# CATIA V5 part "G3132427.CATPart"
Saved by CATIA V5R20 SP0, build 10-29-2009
Part number: G3132427
Revision: 3
Definition: design
Nomenclature: G3132427
Source: made
Description: NOT SPECIFIED
Bounding box of the stored display mesh (mm): x -22 to 27, y -17.322 to 17.322, z -17.5 to 17.5
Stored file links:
  C:\Users\Raffaele\Desktop\3D X SITO CF\BOLEX\24-BUSH REF 313\G3132427.CATPart
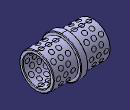
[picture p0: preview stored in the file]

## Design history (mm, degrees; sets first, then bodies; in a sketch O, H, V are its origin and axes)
Body1 "MANIFOLD_SOLID_BREP #11589" (main body)
  Solid1: solid without history
Body2 "MANIFOLD_SOLID_BREP #11740"
  Solid2: solid without history
Body3 "MANIFOLD_SOLID_BREP #11891"
  Solid3: solid without history
Body4 "MANIFOLD_SOLID_BREP #12042"
  Solid4: solid without history
Body5 "MANIFOLD_SOLID_BREP #12193"
  Solid5: solid without history
Body6 "MANIFOLD_SOLID_BREP #12342"
  Solid6: solid without history
Body7 "MANIFOLD_SOLID_BREP #12491"
  Solid7: solid without history
Body8 "MANIFOLD_SOLID_BREP #12640"
  Solid8: solid without history
Body9 "MANIFOLD_SOLID_BREP #12789"
  Solid9: solid without history
Body10 "MANIFOLD_SOLID_BREP #12938"
  Solid10: solid without history
Body11 "MANIFOLD_SOLID_BREP #13087"
  Solid11: solid without history
Body12 "MANIFOLD_SOLID_BREP #13236"
  Solid12: solid without history
Body13 "MANIFOLD_SOLID_BREP #13385"
  Solid13: solid without history
Body14 "MANIFOLD_SOLID_BREP #13534"
  Solid14: solid without history
Body15 "MANIFOLD_SOLID_BREP #13683"
  Solid15: solid without history
Body16 "MANIFOLD_SOLID_BREP #13832"
  Solid16: solid without history
Body17 "MANIFOLD_SOLID_BREP #13981"
  Solid17: solid without history
Body18 "MANIFOLD_SOLID_BREP #14130"
  Solid18: solid without history
Body19 "MANIFOLD_SOLID_BREP #14279"
  Solid19: solid without history
Body20 "MANIFOLD_SOLID_BREP #14428"
  Solid20: solid without history
Body21 "MANIFOLD_SOLID_BREP #14577"
  Solid21: solid without history
Body22 "MANIFOLD_SOLID_BREP #14726"
  Solid22: solid without history
Body23 "MANIFOLD_SOLID_BREP #14875"
  Solid23: solid without history
Body24 "MANIFOLD_SOLID_BREP #15024"
  Solid24: solid without history
Body25 "MANIFOLD_SOLID_BREP #15173"
  Solid25: solid without history
Body26 "MANIFOLD_SOLID_BREP #15322"
  Solid26: solid without history
Body27 "MANIFOLD_SOLID_BREP #15471"
  Solid27: solid without history
Body28 "MANIFOLD_SOLID_BREP #15620"
  Solid28: solid without history
Body29 "MANIFOLD_SOLID_BREP #15769"
  Solid29: solid without history
Body30 "MANIFOLD_SOLID_BREP #15918"
  Solid30: solid without history
Body31 "MANIFOLD_SOLID_BREP #16067"
  Solid31: solid without history
Body32 "MANIFOLD_SOLID_BREP #16218"
  Solid32: solid without history
Body33 "MANIFOLD_SOLID_BREP #16369"
  Solid33: solid without history
Body34 "MANIFOLD_SOLID_BREP #16518"
  Solid34: solid without history
Body35 "MANIFOLD_SOLID_BREP #16667"
  Solid35: solid without history
Body36 "MANIFOLD_SOLID_BREP #16816"
  Solid36: solid without history
Body37 "MANIFOLD_SOLID_BREP #16965"
  Solid37: solid without history
Body38 "MANIFOLD_SOLID_BREP #17114"
  Solid38: solid without history
Body39 "MANIFOLD_SOLID_BREP #17263"
  Solid39: solid without history
Body40 "MANIFOLD_SOLID_BREP #17412"
  Solid40: solid without history
Body41 "MANIFOLD_SOLID_BREP #17561"
  Solid41: solid without history
Body42 "MANIFOLD_SOLID_BREP #17710"
  Solid42: solid without history
Body43 "MANIFOLD_SOLID_BREP #17859"
  Solid43: solid without history
Body44 "MANIFOLD_SOLID_BREP #18008"
  Solid44: solid without history
Body45 "MANIFOLD_SOLID_BREP #18157"
  Solid45: solid without history
Body46 "MANIFOLD_SOLID_BREP #18306"
  Solid46: solid without history
Body47 "MANIFOLD_SOLID_BREP #18455"
  Solid47: solid without history
Body48 "MANIFOLD_SOLID_BREP #18604"
  Solid48: solid without history
Body49 "MANIFOLD_SOLID_BREP #18753"
  Solid49: solid without history
Body50 "MANIFOLD_SOLID_BREP #18902"
  Solid50: solid without history
Body51 "MANIFOLD_SOLID_BREP #19051"
  Solid51: solid without history
Body52 "MANIFOLD_SOLID_BREP #19200"
  Solid52: solid without history
Body53 "MANIFOLD_SOLID_BREP #19349"
  Solid53: solid without history
Body54 "MANIFOLD_SOLID_BREP #19498"
  Solid54: solid without history
Body55 "MANIFOLD_SOLID_BREP #19647"
  Solid55: solid without history
Body56 "MANIFOLD_SOLID_BREP #19796"
  Solid56: solid without history
Body57 "MANIFOLD_SOLID_BREP #19945"
  Solid57: solid without history
Body58 "MANIFOLD_SOLID_BREP #20094"
  Solid58: solid without history
Body59 "MANIFOLD_SOLID_BREP #20243"
  Solid59: solid without history
Body60 "MANIFOLD_SOLID_BREP #20394"
  Solid60: solid without history
Body61 "MANIFOLD_SOLID_BREP #20545"
  Solid61: solid without history
Body62 "MANIFOLD_SOLID_BREP #20696"
  Solid62: solid without history
Body63 "MANIFOLD_SOLID_BREP #20847"
  Solid63: solid without history
Body64 "MANIFOLD_SOLID_BREP #20998"
  Solid64: solid without history
Body65 "MANIFOLD_SOLID_BREP #21149"
  Solid65: solid without history
Body66 "MANIFOLD_SOLID_BREP #21298"
  Solid66: solid without history
Body67 "MANIFOLD_SOLID_BREP #21447"
  Solid67: solid without history
Body68 "MANIFOLD_SOLID_BREP #21596"
  Solid68: solid without history
Body69 "MANIFOLD_SOLID_BREP #21745"
  Solid69: solid without history
Body70 "MANIFOLD_SOLID_BREP #21894"
  Solid70: solid without history
Body71 "MANIFOLD_SOLID_BREP #22043"
  Solid71: solid without history
Body72 "MANIFOLD_SOLID_BREP #22192"
  Solid72: solid without history
Body73 "MANIFOLD_SOLID_BREP #22341"
  Solid73: solid without history
Body74 "MANIFOLD_SOLID_BREP #22490"
  Solid74: solid without history
Body75 "MANIFOLD_SOLID_BREP #22639"
  Solid75: solid without history
Body76 "MANIFOLD_SOLID_BREP #22788"
  Solid76: solid without history
Body77 "MANIFOLD_SOLID_BREP #22937"
  Solid77: solid without history
Body78 "MANIFOLD_SOLID_BREP #23086"
  Solid78: solid without history
Body79 "MANIFOLD_SOLID_BREP #23235"
  Solid79: solid without history
Body80 "MANIFOLD_SOLID_BREP #23384"
  Solid80: solid without history
Body81 "MANIFOLD_SOLID_BREP #23533"
  Solid81: solid without history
